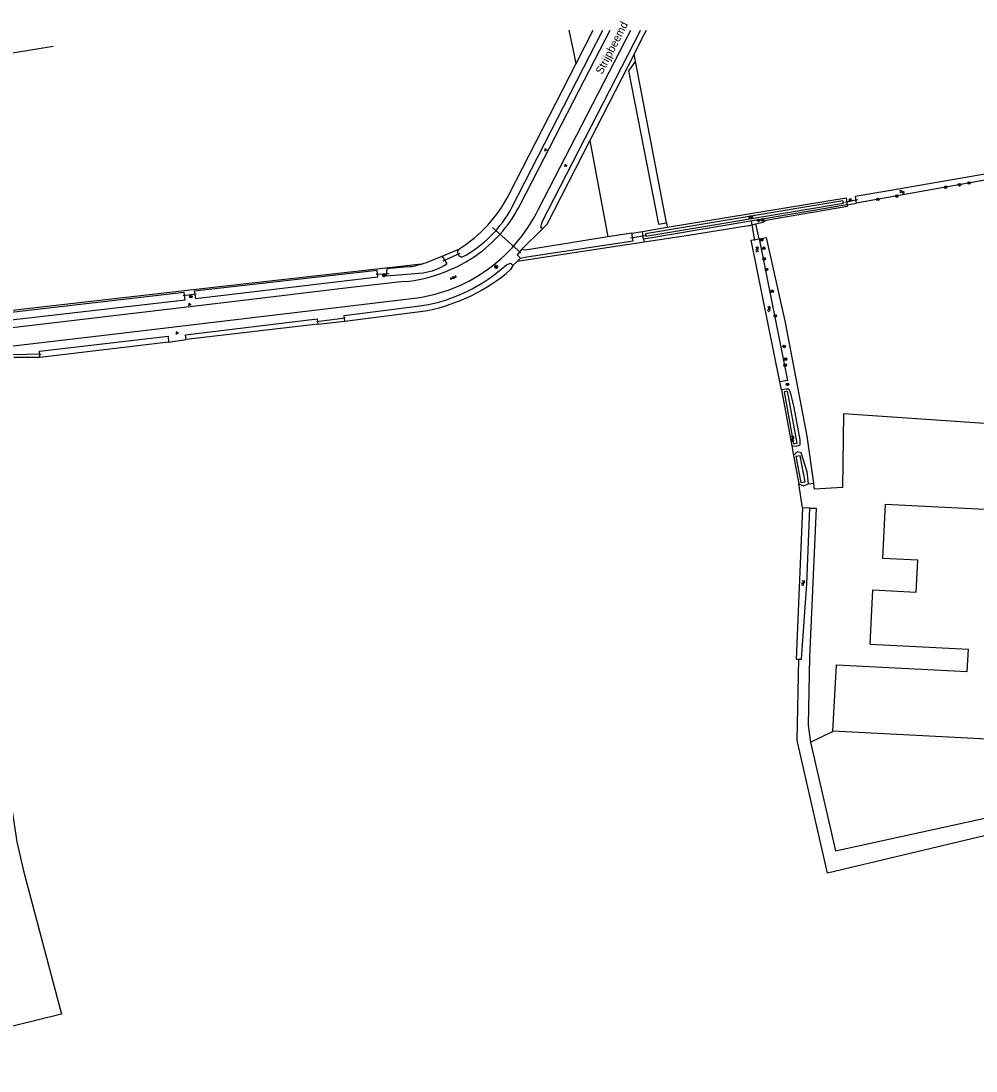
# Model space of a CAD drawing. Extents: x 124000 to 129000, y 395500 to 397503.
# Drawn here: x 126314 to 126612.4, y 397175 to 397502.9 of the extents above; entities that cross this region are included whole.
import ezdxf

# ---------------------------------------------------------------- set-up
doc = ezdxf.new("R2010")
doc.units = 0
for name, color, linetype in [('gg-afsc-draadraster', 7, 'Continuous'), ('gg-afsc-lijn draadraster', 7, 'Continuous'), ('gg-anno-openbare ruimte label', 7, 'Continuous'), ('gg-bbg-hoofdgebouw', 7, 'Continuous'), ('gg-knt-bronhoudergrens', 7, 'Continuous'), ('gg-knt-verharding', 7, 'Continuous'), ('gg-kntw-bovenkant insteek waterloop', 7, 'Continuous'), ('gg-kntw-greppel-droge sloot', 7, 'Continuous'), ('gg-kntw-waterlijn', 7, 'Continuous'), ('gg-kwrk-duiker nz buis', 7, 'Continuous'), ('gt-grn-groengrens', 7, 'Continuous'), ('gt-grn-vlakafsluiter', 7, 'Continuous'), ('gt-symb-boom', 7, 'Continuous'), ('gt-symb-gesloten verharding', 7, 'Continuous'), ('gt-symb-groenvak', 7, 'Continuous'), ('gt-symb-lichtmast', 7, 'Continuous'), ('gt-symb-watersymbool', 7, 'Continuous'), ('gx-grn-maaiveld', 7, 'Continuous')]:
    doc.layers.add(name, color=color, linetype=linetype)

# ---------------------------------------------------------------- blocks, each defined once
blk = doc.blocks.new('gt0-WA')
at = {"layer": 'gt-symb-watersymbool'}
for centre, start, end in [((-0.32, 0.02), 28.0725, 151.9275), ((0.43, 0.42), 208.0725, 331.9275), ((-0.32, -0.43), 28.0725, 151.9275), ((0.43, -0.03), 208.0725, 331.9275)]:
    blk.add_arc(centre, 0.425, start, end, dxfattribs=at)
blk = doc.blocks.new('gt0-BOOM')
at = {"layer": 'gt-symb-boom'}
for radius in [0.4, 0.2]:
    blk.add_circle((0, 0), radius, dxfattribs=at)
blk = doc.blocks.new('gt0-GRVAK')
at = {"layer": 'gt-symb-groenvak'}
for p, q in [((-0.11, 0.19), (-0.23, 0.24)), ((-0.18, 0.15), (0.09, 0.15)), ((-0.09, 0.21), (-0.16, 0.32)), ((-0.05, 0.21), (-0.05, 0.39)), ((0, 0.21), (0.06, 0.32)), ((0.01, 0.19), (0.13, 0.24)), ((0.26, -0.05), (0.2, 0.06)), ((0.3, -0.05), (0.3, 0.13)), ((0.35, -0.05), (0.41, 0.06)), ((-0.25, -0.23), (-0.36, -0.18)), ((-0.32, -0.26), (-0.05, -0.26)), ((-0.23, -0.21), (-0.29, -0.09)), ((-0.18, -0.2), (-0.18, -0.02)), ((-0.14, -0.21), (-0.07, -0.09)), ((-0.12, -0.23), (0, -0.18)), ((0.24, -0.07), (0.12, -0.02)), ((0.17, -0.11), (0.44, -0.11)), ((0.37, -0.07), (0.49, -0.02))]:
    blk.add_line(p, q, dxfattribs=at)
blk = doc.blocks.new('gt0-GESVH1')
at = {"layer": 'gt-symb-gesloten verharding'}
for p, q in [((-0.99, -0.26), (0.01, 0.24)), ((0.01, -0.26), (-0.99, 0.24)), ((0.01, 0.24), (1.01, -0.26)), ((1.01, 0.24), (0.01, -0.26))]:
    blk.add_line(p, q, dxfattribs=at)
blk = doc.blocks.new('gt0-LMAST')
at = {"layer": 'gt-symb-lichtmast'}
for p, q in [((-0.18, 0.17), (-0.45, 0.44)), ((-0.01, 0.25), (-0.01, 0.62)), ((0.17, 0.17), (0.44, 0.44)), ((-0.26, 0), (-0.63, 0)), ((-0.18, -0.18), (-0.45, -0.45)), ((-0.01, -0.25), (-0.01, -0.63)), ((0.44, -0.45), (0.17, -0.18)), ((0.24, 0), (0.62, 0))]:
    blk.add_line(p, q, dxfattribs=at)
blk.add_circle((-0.01, 0), 0.25, dxfattribs=at)

msp = doc.modelspace()

# ---------------------------------------------------------------- linework, layer by layer
at = {"layer": 'gg-afsc-draadraster'}
for p, q in [((126551.61, 397387.68), (126551.15, 397390.18)), ((126558.14, 397350.84), (126557, 397358.39)), ((126647.69, 397256.21), (126565.95, 397236.81))]:
    msp.add_line(p, q, dxfattribs=at)
for points in [[(126545.83, 397440.08), (126546.74, 397440.73), (126572.21, 397445.1), (126572.14, 397445.55)], [(126561.72, 397358.54), (126559.66, 397373.27), (126552.83, 397408.76), (126546.91, 397435.26)], [(126670, 397374.12), (126646.79, 397376.43), (126613.6, 397377.29), (126570.97, 397380.21), (126570.71, 397357.19), (126561.98, 397356.66), (126561.72, 397358.54)], [(126565.95, 397236.81), (126556.51, 397278.25), (126557.02, 397303.63)]]:
    msp.add_lwpolyline(points, dxfattribs=at)
at = {"layer": 'gg-afsc-lijn draadraster'}
for p, q in [((126551.61, 397387.68), (126551.15, 397390.18)), ((126558.14, 397350.84), (126557, 397358.39)), ((126647.69, 397256.21), (126565.95, 397236.81))]:
    msp.add_line(p, q, dxfattribs=at)
for points in [[(126278.2, 397500), (126280.71, 397487.99), (126324.08, 397495.07)], [(126565.95, 397236.81), (126556.51, 397278.25), (126557.02, 397303.63)]]:
    msp.add_lwpolyline(points, dxfattribs=at)
at = {"layer": 'gg-bbg-hoofdgebouw'}
for p, q in [((126579.34, 397308.32), (126580.2, 397325.25)), ((126579.34, 397308.32), (126610.02, 397306.77)), ((126626.68, 397278.1), (126567.71, 397281.12))]:
    msp.add_line(p, q, dxfattribs=at)
for points in [[(126584.12, 397352.02), (126637.7, 397349.34), (126638.63, 397367.79), (126644.3, 397367.48)], [(126594.26, 397334.52), (126583.26, 397335.09), (126584.12, 397352.02)], [(126580.2, 397325.25), (126593.74, 397324.55), (126594.26, 397334.52)], [(126567.71, 397281.12), (126568.76, 397301.89), (126609.66, 397299.79), (126610.02, 397306.77)]]:
    msp.add_lwpolyline(points, dxfattribs=at)
at = {"layer": 'gg-knt-bronhoudergrens'}
for p, q in [((126485.19, 397500), (126486.79, 397492.24)), ((126505.99, 397490.33), (126505.57, 397492.51)), ((126572.14, 397445.55), (126575, 397446.04)), ((126515.68, 397439.86), (126515.94, 397438.48)), ((126541.28, 397438.96), (126543.55, 397439.52)), ((126543.55, 397439.52), (126545.83, 397440.08)), ((126544.64, 397434.87), (126543.55, 397439.52)), ((126544.64, 397434.87), (126546.91, 397435.26)), ((126508.67, 397433.87), (126468.99, 397427.84)), ((126560.06, 397358.34), (126561.72, 397358.54))]:
    msp.add_line(p, q, dxfattribs=at)
for points in [[(126541.28, 397438.96), (126522.53, 397435.97), (126508.67, 397433.87)], [(126560.44, 397350.75), (126562.45, 397350.75), (126560.37, 397304.26), (126559.91, 397282.98), (126560.68, 397277.71)], [(126560.68, 397277.71), (126567.36, 397280.87), (126567.71, 397281.12)], [(126560.68, 397277.71), (126568.48, 397243.77), (126646.12, 397260.75), (126647.69, 397256.21)]]:
    msp.add_lwpolyline(points, dxfattribs=at)
at = {"layer": 'gg-knt-verharding'}
msp.add_line((126475.66, 397444.15), (126504.51, 397500), dxfattribs=at)
for points in [[(126470.05, 397445.73), (126490.08, 397484.49), (126498.11, 397500)], [(126433.69, 397421.51), (126418, 397419.74), (126379.03, 397415.1), (126321.87, 397408.35), (126272.82, 397402.64), (126235.67, 397398.26), (126221.34, 397397.21)], [(126223.02, 397390.27), (126228.23, 397391.47), (126284, 397398.26), (126340.02, 397404.77), (126395.97, 397411.41), (126437.83, 397416.48)]]:
    msp.add_lwpolyline(points, dxfattribs=at)
for centre, radius, start, end in [((126431.56, 397465.03), 43.06, 306.4825, 333.3655), ((126430.32, 397466.3), 50.46, 304.3668, 333.9639), ((126429.24, 397468.62), 47.32, 275.3984, 306.1598), ((126430.81, 397465.52), 49.54, 278.1438, 304.4039)]:
    msp.add_arc(centre, radius, start, end, dxfattribs=at)
at = {"layer": 'gg-kntw-bovenkant insteek waterloop'}
for p, q in [((126641.94, 397458.02), (126575, 397446.04)), ((126508.17, 397437.21), (126515.94, 397438.48)), ((126508.54, 397434.76), (126508.17, 397437.21)), ((126551.61, 397387.68), (126554.83, 397370.22)), ((126555.37, 397367.26), (126557, 397358.39)), ((126560.44, 397350.75), (126558.14, 397350.84))]:
    msp.add_line(p, q, dxfattribs=at)
for points in [[(126641.94, 397458.02), (126641.64, 397459.7), (126584.5, 397449.73), (126574.65, 397448.11), (126575, 397446.04)], [(126515.94, 397438.48), (126571.78, 397447.64), (126572.14, 397445.55)], [(126572.14, 397445.55), (126510.48, 397435.05), (126508.54, 397434.76)], [(126551.15, 397390.18), (126542.19, 397434.44), (126544.64, 397434.87)], [(126544.64, 397434.87), (126553.45, 397390.61), (126551.15, 397390.18)], [(126554.83, 397370.22), (126556.22, 397370.09), (126557.41, 397370.52), (126557.47, 397372.1), (126555.61, 397382.16), (126554.4, 397387.03), (126553.92, 397387.98), (126552.94, 397387.93), (126551.61, 397387.68)], [(126560.06, 397358.34), (126559.69, 397362.1), (126557.78, 397368.03), (126556.55, 397368.34), (126555.37, 397367.26)], [(126557, 397358.39), (126558.49, 397357.78), (126560.06, 397358.34)], [(126558.14, 397350.84), (126556.24, 397303.66), (126557.02, 397303.63)], [(126557.02, 397303.63), (126557.82, 397303.6), (126559.49, 397327.16), (126560.44, 397350.75)]]:
    msp.add_lwpolyline(points, dxfattribs=at)
at = {"layer": 'gg-kntw-greppel-droge sloot'}
for p, q in [((126467.48, 397444.84), (126495.81, 397500)), ((126487.36, 397489.45), (126492.78, 397500)), ((126505.57, 397492.51), (126491.77, 397465.59)), ((126505.99, 397490.33), (126503.79, 397487.38)), ((126515.68, 397439.86), (126505.99, 397490.33)), ((126466.49, 397448.82), (126487.36, 397489.45)), ((126504.86, 397436.68), (126497.32, 397435.48)), ((126442.25, 397428.08), (126445.64, 397429.51)), ((126445.64, 397429.51), (126447.04, 397427.05)), ((126467.63, 397426.54), (126466.94, 397425.27)), ((126415.19, 397409.14), (126441.07, 397412.54)), ((126406.7, 397408.27), (126365.58, 397403.4)), ((126360.09, 397402.6), (126319.93, 397397.86))]:
    msp.add_line(p, q, dxfattribs=at)
for points in [[(126476.95, 397438.05), (126476.4, 397438.38), (126476.8, 397440.23), (126507.41, 397499.73), (126507.55, 397500)], [(126505.57, 397492.51), (126508.74, 397498.68), (126509.43, 397500)], [(126503.79, 397487.38), (126513.15, 397439.48), (126515.68, 397439.86)], [(126491.77, 397465.59), (126478.3, 397439.31), (126476.95, 397438.05)], [(126470.05, 397428.85), (126472.02, 397429.22), (126505.23, 397434.25), (126504.86, 397436.68)], [(126497.32, 397435.48), (126471.61, 397431.38), (126470.4, 397431.51)], [(126470.4, 397431.51), (126469.01, 397429.86), (126470.05, 397428.85)], [(126368.13, 397418.49), (126368.54, 397416.27), (126425.45, 397423.04), (126425.26, 397424.98), (126368.13, 397418.49)], [(126434.91, 397426.12), (126428.35, 397425.5), (126428.05, 397423.32), (126439.61, 397424.3)], [(126462.33, 397424.04), (126465.73, 397426.71), (126466.92, 397427.26), (126467.63, 397426.54)], [(126223.5, 397401.22), (126223.24, 397399.71), (126229, 397399.65), (126235.3, 397400.21), (126243.75, 397401.89), (126365.26, 397415.8), (126365.02, 397418.09), (126223.58, 397401.73)], [(126415.19, 397409.14), (126414.95, 397410.9), (126437.82, 397413.83), (126441.29, 397414.37)], [(126365.58, 397403.4), (126365.42, 397404.92), (126406.5, 397409.88), (126406.7, 397408.27)], [(126319.93, 397397.86), (126319.73, 397399.84), (126359.98, 397404.46), (126360.09, 397402.6)]]:
    msp.add_lwpolyline(points, dxfattribs=at)
for centre, radius, start, end in [((126428.28, 397468.04), 42.77, 301.7952, 333.2882), ((126434.21, 397462.37), 37.6, 298.1905, 332.211), ((126451.88, 397430.69), 1.47, 136.8046, 273.7318), ((126431.41, 397453.83), 27.93, 286.0911, 292.8142), ((126431.42, 397453.8), 27.9, 277.1758, 286.0869), ((126437.32, 397441.91), 17.76, 277.4186, 303.1975), ((126429.96, 397467.77), 56.34, 281.3747, 311.0267), ((126431.07, 397464.35), 51.01, 281.5549, 307.7925)]:
    msp.add_arc(centre, radius, start, end, dxfattribs=at)
at = {"layer": 'gg-kntw-waterlijn'}
for points in [[(126509.12, 397436.45), (126509.23, 397435.67), (126570.94, 397446.02), (126570.82, 397446.77), (126509.12, 397436.45)], [(126552.42, 397387.15), (126555.42, 397370.89), (126556.51, 397371.09), (126553.52, 397387.31), (126552.42, 397387.15)], [(126556.12, 397366.86), (126557.68, 397358.76), (126558.98, 397359.01), (126557.41, 397367.1), (126556.12, 397366.86)]]:
    msp.add_lwpolyline(points, dxfattribs=at)
at = {"layer": 'gg-kwrk-duiker nz buis'}
for p, q in [((126575.48, 397447.09), (126571.37, 397446.2)), ((126461.29, 397438.44), (126470.22, 397430.49)), ((126542.09, 397440.45), (126543.2, 397434.32)), ((126504.41, 397435.18), (126509.04, 397435.89)), ((126445.86, 397428.01), (126451.25, 397430.43)), ((126424.93, 397423.84), (126429, 397424.05)), ((126368.78, 397417.65), (126364.7, 397417.08)), ((126406.32, 397409.06), (126415.26, 397410.16)), ((126311.31, 397398.75), (126320.3, 397398.97))]:
    msp.add_line(p, q, dxfattribs=at)
at = {"layer": 'gt-grn-groengrens'}
for p, q in [((126486.79, 397492.24), (126487.36, 397489.45)), ((126491.77, 397465.59), (126497.32, 397435.48)), ((126470.4, 397431.51), (126476.95, 397438.05)), ((126504.86, 397436.68), (126508.17, 397437.21)), ((126445.64, 397429.51), (126450.82, 397431.69)), ((126467.63, 397426.54), (126468.99, 397427.84)), ((126468.99, 397427.84), (126470.05, 397428.85)), ((126406.7, 397408.27), (126415.19, 397409.14)), ((126360.09, 397402.6), (126365.58, 397403.4)), ((126319.93, 397397.86), (126311.78, 397397.85))]:
    msp.add_line(p, q, dxfattribs=at)
msp.add_lwpolyline([(126439.16, 397426.99), (126376, 397419.86), (126285.64, 397409.54), (126262.89, 397407.42), (126247.48, 397405.57), (126233.19, 397403.52), (126224.1, 397401.89), (126223.58, 397401.73)], dxfattribs=at)
at = {"layer": 'gt-grn-vlakafsluiter'}
for p, q in [((126508.54, 397434.76), (126508.67, 397433.87)), ((126554.83, 397370.22), (126555.37, 397367.26))]:
    msp.add_line(p, q, dxfattribs=at)
at = {"layer": 'gx-grn-maaiveld'}
msp.add_lwpolyline([(126308.42, 397275.79), (126310.09, 397263.89), (126312.7, 397246.54), (126314.76, 397237.48), (126326.66, 397192.75), (126254.64, 397175)], dxfattribs=at)

# ---------------------------------------------------------------- block references
at = {"layer": 'gt-symb-boom'}
for p in [(126602.89, 397450.98), (126607.24, 397451.77), (126610.19, 397452.31), (126573.14, 397447.03), (126581.72, 397447.21), (126587.65, 397448.23), (126544.41, 397440.63), (126545.69, 397440.79), (126545.45, 397434.51), (126546.08, 397431.93), (126546.23, 397428.63), (126546.95, 397425.33), (126427.43, 397423.41), (126548.7, 397418.51), (126367.06, 397416.83), (126549.69, 397410.85), (126552.47, 397401.28), (126552.78, 397395.41), (126552.9, 397397.31), (126553.5, 397389.42)]:
    msp.add_blockref('gt0-BOOM', p, dxfattribs=at)
at = {"layer": 'gt-symb-gesloten verharding', "rotation": 26.180521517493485}
msp.add_blockref('gt0-GESVH1', (126449.07, 397422.76), dxfattribs=at)
at = {"layer": 'gt-symb-groenvak'}
for p in [(126477.91, 397462.74), (126484.17, 397457.82), (126366.65, 397414.44), (126362.72, 397405.51)]:
    msp.add_blockref('gt0-GRVAK', p, dxfattribs=at)
at = {"layer": 'gt-symb-lichtmast'}
msp.add_blockref('gt0-LMAST', (126462.51, 397426.14), dxfattribs=at)
at = {"layer": 'gt-symb-watersymbool'}
for p, rotation in [((126589.22, 397449.54), 9.377579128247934), ((126542.09, 397441.61), -170.3304947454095), ((126544.01, 397431.65), -78.28547478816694), ((126547.74, 397412.99), -78.28547478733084), ((126555.12, 397372.52), -79.56697526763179), ((126558.38, 397327.45), -94.0121711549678)]:
    msp.add_blockref('gt0-WA', p, dxfattribs=dict(at, rotation=rotation))

# ---------------------------------------------------------------- texts
at = {"layer": 'gg-anno-openbare ruimte label'}
msp.add_text('Strijpbeemd', height=2.5, rotation=62.7, dxfattribs=at).set_placement((126495.59, 397486.05))

doc.saveas('drawing.dxf')
